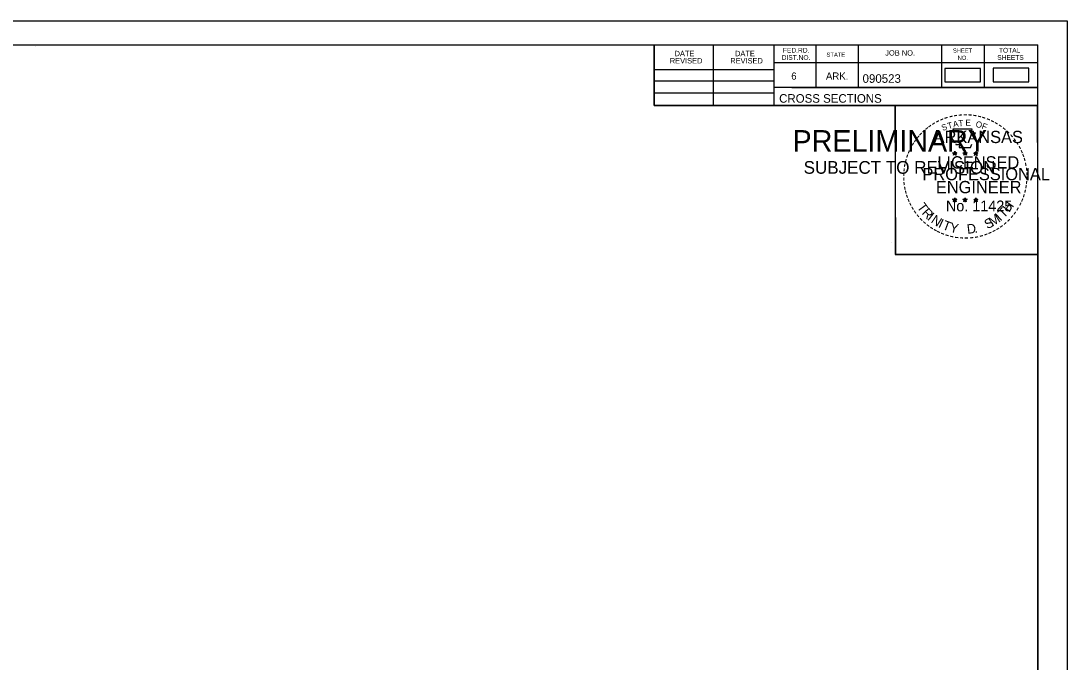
# Model space of a CAD drawing. Extents: x 1406028 to 1412453, y 321733 to 325986.
# Drawn here: x 1406582.1 to 1406752.8, y 323108.1 to 323212.7 of the extents above; entities that cross this region are included whole.
import ezdxf

# ---------------------------------------------------------------- set-up
doc = ezdxf.new("R2010")
doc.units = 0
for name, color, linetype in [('R_Border', 7, 'Continuous'), ('R_Border PE', 7, 'Continuous'), ('R_Border Prem', 7, 'Continuous'), ('R_Fin Surface', 7, 'Continuous'), ('R_No Plot', 7, 'Continuous')]:
    doc.layers.add(name, color=color, linetype=linetype)

msp = doc.modelspace()

# ---------------------------------------------------------------- linework, layer by layer
at = {"layer": 'R_Border'}
for p, q in [((1406431.89, 323208.8), (1406748.07, 323208.8)), ((1406685.43, 323198.92), (1406685.43, 323208.8)), ((1406695.11, 323198.92), (1406695.11, 323208.8)), ((1406704.97, 323208.8), (1406704.97, 323198.92)), ((1406711.81, 323208.8), (1406711.81, 323201.86)), ((1406718.75, 323208.8), (1406718.75, 323201.86)), ((1406732.33, 323208.8), (1406732.33, 323201.86)), ((1406739.27, 323208.8), (1406739.27, 323201.86)), ((1406748.07, 323003.34), (1406748.07, 323208.8)), ((1406584.41, 323208.54), (1406584.41, 323208.54)), ((1406584.41, 323208.54), (1406584.41, 323208.54)), ((1406748.07, 323205.86), (1406704.97, 323205.86)), ((1406748.07, 323205.88), (1406748.07, 323205.88)), ((1406685.43, 323204.78), (1406704.97, 323204.78)), ((1406685.43, 323202.92), (1406704.97, 323202.92)), ((1406685.43, 323200.98), (1406704.97, 323200.98)), ((1406748.07, 323201.86), (1406704.97, 323201.86)), ((1406707.93, 323201.86), (1406748.07, 323201.86)), ((1406748.07, 323198.92), (1406685.43, 323198.92))]:
    msp.add_line(p, q, dxfattribs=at)
at = {"layer": 'R_Border PE'}
for p, q in [((1406734.15, 323191.18), (1406734.5, 323191.07)), ((1406734.15, 323191.18), (1406734.41, 323191.13)), ((1406734.15, 323191.18), (1406734.39, 323191.05)), ((1406734.29, 323190.77), (1406734.5, 323191.07)), ((1406734.29, 323190.77), (1406734.41, 323191.01)), ((1406734.29, 323190.77), (1406734.5, 323190.99)), ((1406734.5, 323191.43), (1406734.46, 323191.18)), ((1406734.5, 323191.07), (1406734.5, 323191.43)), ((1406734.5, 323191.43), (1406734.55, 323191.18)), ((1406734.85, 323191.18), (1406734.5, 323191.07)), ((1406734.72, 323190.77), (1406734.5, 323191.07)), ((1406734.72, 323190.77), (1406734.5, 323190.98)), ((1406734.85, 323191.18), (1406734.56, 323191.13)), ((1406734.72, 323190.77), (1406734.58, 323191.06)), ((1406734.85, 323191.18), (1406734.65, 323191.07)), ((1406735.82, 323191.18), (1406736.17, 323191.07)), ((1406735.82, 323191.18), (1406736.08, 323191.13)), ((1406735.82, 323191.18), (1406736.06, 323191.05)), ((1406735.96, 323190.77), (1406736.17, 323191.07)), ((1406735.96, 323190.77), (1406736.08, 323191.01)), ((1406735.96, 323190.77), (1406736.17, 323190.99)), ((1406736.17, 323191.43), (1406736.13, 323191.18)), ((1406736.17, 323191.07), (1406736.17, 323191.43)), ((1406736.17, 323191.43), (1406736.22, 323191.18)), ((1406736.52, 323191.18), (1406736.17, 323191.07)), ((1406736.39, 323190.77), (1406736.17, 323191.07)), ((1406736.39, 323190.77), (1406736.17, 323190.98)), ((1406736.52, 323191.18), (1406736.23, 323191.13)), ((1406736.39, 323190.77), (1406736.25, 323191.06)), ((1406736.52, 323191.18), (1406736.32, 323191.07)), ((1406737.59, 323191.16), (1406737.94, 323191.05)), ((1406737.59, 323191.16), (1406737.84, 323191.12)), ((1406737.59, 323191.16), (1406737.83, 323191.04)), ((1406737.72, 323190.76), (1406737.94, 323191.05)), ((1406737.72, 323190.76), (1406737.85, 323191)), ((1406737.72, 323190.76), (1406737.94, 323190.97)), ((1406737.94, 323191.42), (1406737.9, 323191.17)), ((1406737.94, 323191.05), (1406737.94, 323191.42)), ((1406737.94, 323191.42), (1406737.99, 323191.17)), ((1406738.28, 323191.16), (1406737.94, 323191.05)), ((1406738.15, 323190.76), (1406737.94, 323191.05)), ((1406738.15, 323190.76), (1406737.94, 323190.97)), ((1406738.28, 323191.16), (1406738, 323191.12)), ((1406738.15, 323190.76), (1406738.01, 323191.05)), ((1406738.28, 323191.16), (1406738.08, 323191.06)), ((1406734.15, 323183.6), (1406734.5, 323183.49)), ((1406734.15, 323183.6), (1406734.4, 323183.56)), ((1406734.15, 323183.6), (1406734.39, 323183.48)), ((1406734.28, 323183.2), (1406734.5, 323183.49)), ((1406734.28, 323183.2), (1406734.41, 323183.44)), ((1406734.28, 323183.2), (1406734.5, 323183.41)), ((1406734.5, 323183.86), (1406734.46, 323183.61)), ((1406734.5, 323183.49), (1406734.5, 323183.86)), ((1406734.5, 323183.86), (1406734.55, 323183.61)), ((1406734.85, 323183.6), (1406734.5, 323183.49)), ((1406734.71, 323183.2), (1406734.5, 323183.49)), ((1406734.71, 323183.2), (1406734.5, 323183.41)), ((1406734.85, 323183.6), (1406734.56, 323183.55)), ((1406734.71, 323183.2), (1406734.58, 323183.49)), ((1406734.85, 323183.6), (1406734.64, 323183.5)), ((1406735.82, 323183.6), (1406736.17, 323183.49)), ((1406735.82, 323183.6), (1406736.07, 323183.56)), ((1406735.82, 323183.6), (1406736.06, 323183.48)), ((1406735.95, 323183.2), (1406736.17, 323183.49)), ((1406735.95, 323183.2), (1406736.08, 323183.44)), ((1406735.95, 323183.2), (1406736.17, 323183.41)), ((1406736.17, 323183.86), (1406736.13, 323183.61)), ((1406736.17, 323183.49), (1406736.17, 323183.86)), ((1406736.17, 323183.86), (1406736.22, 323183.61)), ((1406736.52, 323183.6), (1406736.17, 323183.49)), ((1406736.38, 323183.2), (1406736.17, 323183.49)), ((1406736.38, 323183.2), (1406736.17, 323183.41)), ((1406736.52, 323183.6), (1406736.23, 323183.55)), ((1406736.38, 323183.2), (1406736.24, 323183.49)), ((1406736.52, 323183.6), (1406736.31, 323183.5)), ((1406737.59, 323183.59), (1406737.94, 323183.48)), ((1406737.59, 323183.59), (1406737.84, 323183.55)), ((1406737.59, 323183.59), (1406737.82, 323183.47)), ((1406737.72, 323183.19), (1406737.94, 323183.48)), ((1406737.72, 323183.19), (1406737.85, 323183.43)), ((1406737.72, 323183.19), (1406737.93, 323183.4)), ((1406737.94, 323183.85), (1406737.89, 323183.6)), ((1406738.15, 323183.19), (1406737.93, 323183.4)), ((1406737.94, 323183.48), (1406737.94, 323183.85)), ((1406737.94, 323183.85), (1406737.98, 323183.6)), ((1406738.28, 323183.59), (1406737.94, 323183.48)), ((1406738.15, 323183.19), (1406737.94, 323183.48)), ((1406738.28, 323183.59), (1406738, 323183.54)), ((1406738.15, 323183.19), (1406738.01, 323183.48)), ((1406738.28, 323183.59), (1406738.08, 323183.49))]:
    msp.add_line(p, q, dxfattribs=at)
for points in [[(1406734.2, 323195.05), (1406734.46, 323194.23)], [(1406737.71, 323194.13), (1406737.85, 323194.42), (1406737.16, 323194.39), (1406737.31, 323195.05), (1406734.2, 323195.05)], [(1406734.69, 323192.63), (1406734.69, 323192.54), (1406735.25, 323192.53), (1406735.2, 323192.05), (1406737.07, 323192.05), (1406737.27, 323192.59)], [(1406734.5, 323191.43), (1406734.72, 323190.77), (1406734.15, 323191.18), (1406734.85, 323191.18), (1406734.29, 323190.77), (1406734.5, 323191.43)], [(1406736.17, 323191.43), (1406736.39, 323190.77), (1406735.82, 323191.18), (1406736.52, 323191.18), (1406735.96, 323190.77), (1406736.17, 323191.43)], [(1406737.94, 323191.42), (1406738.15, 323190.76), (1406737.59, 323191.16), (1406738.28, 323191.16), (1406737.72, 323190.76), (1406737.94, 323191.42)], [(1406734.5, 323183.86), (1406734.71, 323183.2), (1406734.15, 323183.6), (1406734.85, 323183.6), (1406734.28, 323183.2), (1406734.5, 323183.86)], [(1406736.17, 323183.86), (1406736.38, 323183.2), (1406735.82, 323183.6), (1406736.52, 323183.6), (1406735.95, 323183.2), (1406736.17, 323183.86)], [(1406737.94, 323183.85), (1406738.15, 323183.19), (1406737.59, 323183.59), (1406738.28, 323183.59), (1406737.72, 323183.19), (1406737.94, 323183.85)]]:
    msp.add_lwpolyline(points, dxfattribs=at)
for centre, radius in [((1406734.5, 323191.06), 0.172), ((1406734.5, 323191.06), 0.145), ((1406734.5, 323191.06), 0.116), ((1406734.5, 323191.06), 0.0991), ((1406734.5, 323191.06), 0.0747), ((1406734.5, 323191.06), 0.0495), ((1406734.5, 323191.06), 0.0296), ((1406736.17, 323191.06), 0.172), ((1406736.17, 323191.06), 0.145), ((1406736.17, 323191.06), 0.116), ((1406736.17, 323191.06), 0.0991), ((1406736.17, 323191.06), 0.0747), ((1406736.17, 323191.06), 0.0495), ((1406736.17, 323191.06), 0.0296), ((1406737.94, 323191.05), 0.172), ((1406737.94, 323191.05), 0.145), ((1406737.94, 323191.05), 0.116), ((1406737.94, 323191.05), 0.0991), ((1406737.94, 323191.05), 0.0747), ((1406737.94, 323191.05), 0.0495), ((1406737.94, 323191.05), 0.0296), ((1406734.5, 323183.49), 0.172), ((1406734.5, 323183.49), 0.145), ((1406734.5, 323183.49), 0.116), ((1406734.5, 323183.49), 0.0991), ((1406734.5, 323183.49), 0.0747), ((1406734.5, 323183.49), 0.0495), ((1406734.5, 323183.49), 0.0296), ((1406736.17, 323183.49), 0.172), ((1406736.17, 323183.49), 0.145), ((1406736.17, 323183.49), 0.116), ((1406736.17, 323183.49), 0.0991), ((1406736.17, 323183.49), 0.0747), ((1406736.17, 323183.49), 0.0495), ((1406736.17, 323183.49), 0.0296), ((1406737.93, 323183.48), 0.172), ((1406737.93, 323183.48), 0.145), ((1406737.93, 323183.48), 0.116), ((1406737.93, 323183.48), 0.0991), ((1406737.93, 323183.48), 0.0747), ((1406737.93, 323183.48), 0.0495), ((1406737.93, 323183.48), 0.0296)]:
    msp.add_circle(centre, radius, dxfattribs=at)
at = {"layer": 'R_Fin Surface'}
for points in [[(1406732.85, 323202.75), (1406738.68, 323202.75), (1406738.68, 323204.94), (1406732.85, 323204.94)], [(1406740.76, 323202.78), (1406746.59, 323202.78), (1406746.59, 323204.97), (1406740.76, 323204.97)]]:
    msp.add_lwpolyline(points, close=True, dxfattribs=at)
at = {"layer": 'R_No Plot'}
for p, q in [((1406419.49, 323212.7), (1406752.82, 323212.7)), ((1406724.1, 323176.47), (1406724.1, 323176.47))]:
    msp.add_line(p, q, dxfattribs=at)
for points in [[(1406419.48, 323212.7), (1406752.82, 323212.7), (1406752.82, 322999.36), (1406419.48, 322999.36)], [(1406665.81, 323208.8), (1406685.43, 323208.8), (1406685.43, 323198.92), (1406701.54, 323198.92), (1406724.74, 323198.92), (1406724.74, 323174.59), (1406748.07, 323174.59), (1406748.07, 323003.34), (1406431.89, 323003.34), (1406431.89, 323208.8)], [(1406724.74, 323198.92), (1406747.95, 323198.92), (1406748.07, 323174.59), (1406724.86, 323174.59)]]:
    msp.add_lwpolyline(points, close=True, dxfattribs=at)

# ---------------------------------------------------------------- texts
at = {"layer": 'R_Border'}
for s, height, p in [('DATE', 0.879, (1406688.77, 323206.94)), ('DATE', 0.879, (1406698.63, 323206.94)), ('DIST.NO.', 0.782, (1406706.25, 323206.34)), ('FED.RD.', 0.782, (1406706.45, 323207.52)), ('STATE', 0.684, (1406713.57, 323206.84)), ('JOB NO.', 0.879, (1406723.15, 323207.04)), ('SHEET', 0.684, (1406734.19, 323207.52)), ('SHEETS', 0.782, (1406741.43, 323206.34)), ('TOTAL', 0.782, (1406741.71, 323207.52)), ('REVISED', 0.879, (1406687.99, 323205.76)), ('REVISED', 0.879, (1406697.85, 323205.76)), ('NO.', 0.684, (1406734.97, 323206.34)), ('6', 1.17, (1406707.81, 323203.12)), ('ARK.', 1.172, (1406713.47, 323203.12)), ('090523', 1.4, (1406719.45, 323202.6)), ('CROSS SECTIONS', 1.4, (1406705.83, 323199.35))]:
    msp.add_text(s, height=height, rotation=360, dxfattribs=at).set_placement(p)
at = {"layer": 'R_Border PE'}
for s, height, rotation, p in [('-', 1.6, 19.1761, (1406732.94, 323196.18)), ('-', 1.6, 13.6301, (1406733.69, 323196.42)), ('-', 1.6, 10.2193, (1406734.37, 323196.58)), ('-', 1.6, 5.8968, (1406735.1, 323196.69)), ('-', 1.6, 0.1862, (1406735.87, 323196.77)), ('-', 1.6, 357.743, (1406736.6, 323196.75)), ('-', 1.6, 352.1617, (1406737.34, 323196.7)), ('-', 1.6, 347.2049, (1406738.06, 323196.58)), ('-', 1.6, 342.3362, (1406738.69, 323196.43)), ('-', 1.6, 337.8551, (1406739.43, 323196.21)), ('-', 1.6, 38.9507, (1406730.03, 323194.45)), ('-', 1.6, 36.2317, (1406730.5, 323194.83)), ('-', 1.6, 34.0636, (1406731.08, 323195.23)), ('-', 1.6, 28.7918, (1406731.68, 323195.6)), ('-', 1.6, 24.3072, (1406732.31, 323195.91)), ('S', 1, 21.594, (1406732.55, 323194.73)), ('T', 1, 16.4036, (1406733.46, 323195.06)), ('A', 1, 11.2132, (1406734.29, 323195.31)), ('T', 1, 6.0228, (1406735.14, 323195.48)), ('E', 1, 0.8323, (1406736.24, 323195.59)), ('O', 1, 350.4515, (1406737.85, 323195.38)), ('F', 1, 340.0707, (1406738.8, 323195.15)), ('-', 1.6, 334.1211, (1406740.06, 323195.93)), ('-', 1.6, 329.6409, (1406740.64, 323195.65)), ('-', 1.6, 325.8627, (1406741.28, 323195.29)), ('-', 1.6, 320.5297, (1406741.89, 323194.86)), ('-', 1.6, 54.2325, (1406728.33, 323192.5)), ('-', 1.6, 50.6142, (1406728.74, 323193.07)), ('-', 1.6, 48.423, (1406729.14, 323193.56)), ('-', 1.6, 42.9622, (1406729.59, 323194.04)), ('ARKANSAS', 2, 360, (1406731.05, 323192.77)), ('-', 1.6, 315.5786, (1406742.49, 323194.38)), ('-', 1.6, 309.8797, (1406743.06, 323193.83)), ('-', 1.6, 306.6522, (1406743.58, 323193.22)), ('-', 1.6, 62.8713, (1406727.69, 323191.36)), ('-', 1.6, 58.0706, (1406728, 323191.98)), ('-', 1.4, 303.6753, (1406744.07, 323192.66)), ('-', 1.6, 299.6684, (1406744.39, 323192.05)), ('-', 1.6, 75.461, (1406727.02, 323189.41)), ('-', 1.6, 72.3945, (1406727.21, 323190.12)), ('-', 1.6, 67.7743, (1406727.43, 323190.75)), ('LICENSED', 2, 360, (1406731.65, 323188.62)), ('DWB', 0.01, 360, (1406734.49, 323191.06)), ('DWB', 0.01, 360, (1406736.16, 323191.06)), ('DWB', 0.01, 360, (1406737.92, 323191.05)), ('-', 1.6, 294.6628, (1406744.71, 323191.44)), ('-', 1.6, 290.5728, (1406744.97, 323190.86)), ('-', 1.6, 285.1233, (1406745.2, 323190.28)), ('-', 1.6, 85.1863, (1406726.81, 323188)), ('-', 1.6, 81.2013, (1406726.88, 323188.7)), ('PROFESSIONAL', 2, 360, (1406729.22, 323186.71)), ('-', 1.6, 280.5493, (1406745.4, 323189.54)), ('-', 1.6, 276.5962, (1406745.57, 323188.77)), ('-', 1.6, 94.1959, (1406726.82, 323186.58)), ('-', 1.6, 89.0622, (1406726.78, 323187.3)), ('ENGINEER', 2, 360, (1406731.41, 323184.59)), ('-', 1.6, 263.5172, (1406745.64, 323186.75)), ('-', 1.6, 274.3301, (1406745.63, 323188.05)), ('-', 1.6, 269.9407, (1406745.66, 323187.42)), ('-', 1.6, 98.9479, (1406726.89, 323185.91)), ('-', 1.6, 101.7149, (1406727.02, 323185.18)), ('-', 1.6, 105.4578, (1406727.19, 323184.58)), ('-', 1.6, 255.7626, (1406745.46, 323185.42)), ('-', 1.6, 260.9953, (1406745.57, 323186.1)), ('-', 1.6, 109.0874, (1406727.4, 323183.95)), ('-', 1.6, 114.0643, (1406727.66, 323183.36)), ('T', 1.54, 306.0406, (1406728.26, 323182.33)), ('No. 11425', 1.757, 360, (1406733.04, 323181.64)), ('DWB', 0.01, 360, (1406734.49, 323183.49)), ('DWB', 0.01, 360, (1406736.16, 323183.49)), ('DWB', 0.01, 360, (1406737.92, 323183.48)), ('H', 1.54, 54.6088, (1406743.38, 323181.37)), ('-', 1.6, 247.8887, (1406745.06, 323184.03)), ('-', 1.6, 252.8681, (1406745.28, 323184.7)), ('-', 1.6, 115.7289, (1406727.96, 323182.74)), ('-', 1.6, 120.4471, (1406728.32, 323182.15)), ('-', 1.6, 125.8934, (1406728.72, 323181.59)), ('R', 1.54, 314.005, (1406729.02, 323181.28)), ('T', 1.54, 46.6444, (1406742.49, 323180.42)), ('-', 1.6, 233.8452, (1406744, 323181.99)), ('-', 1.6, 239.0712, (1406744.4, 323182.64)), ('-', 1.6, 244.6197, (1406744.79, 323183.4)), ('-', 1.6, 130.7181, (1406729.18, 323181.04)), ('-', 1.6, 134.2238, (1406729.7, 323180.49)), ('-', 1.6, 138.9338, (1406730.22, 323180.03)), ('I', 1.54, 321.9694, (1406729.92, 323180.35)), ('N', 1.54, 326.5002, (1406730.49, 323179.88)), ('I', 1.54, 335.3603, (1406731.7, 323179.09)), ('T', 1.54, 339.8912, (1406732.36, 323178.77)), ('Y', 1.54, 347.8556, (1406733.58, 323178.32)), ('S', 1.54, 26.9312, (1406739.8, 323178.69)), ('M', 1.54, 32.6563, (1406740.64, 323179.1)), ('I', 1.54, 42.1136, (1406741.93, 323179.95)), ('-', 1.6, 221.0851, (1406742.57, 323180.35)), ('-', 1.6, 225.7653, (1406743.09, 323180.86)), ('-', 1.6, 231.2538, (1406743.57, 323181.43)), ('-', 1.6, 144.6463, (1406730.78, 323179.62)), ('-', 1.6, 148.0898, (1406731.34, 323179.25)), ('-', 1.6, 151.5704, (1406731.92, 323178.93)), ('-', 1.6, 154.6002, (1406732.44, 323178.68)), ('-', 1.6, 158.5612, (1406733.07, 323178.43)), ('D', 1.54, 6.3969, (1406736.56, 323177.96)), ('.', 1.54, 13.7642, (1406737.75, 323178.09)), ('-', 1.6, 204.2516, (1406740.3, 323178.83)), ('-', 1.6, 207.3568, (1406740.93, 323179.15)), ('-', 1.6, 212.2491, (1406741.48, 323179.49)), ('-', 1.6, 215.7363, (1406742.02, 323179.88)), ('-', 1.6, 162.7983, (1406733.75, 323178.21)), ('-', 1.6, 167.5555, (1406734.47, 323178.05)), ('-', 1.6, 173.1155, (1406735.24, 323177.94)), ('-', 1.6, 176.5183, (1406735.99, 323177.89)), ('-', 1.6, 181.5918, (1406736.73, 323177.91)), ('-', 1.6, 185.8167, (1406737.54, 323177.98)), ('-', 1.6, 191.2858, (1406738.28, 323178.11)), ('-', 1.6, 195.4743, (1406739.01, 323178.31)), ('-', 1.6, 200.7184, (1406739.68, 323178.56))]:
    msp.add_text(s, height=height, rotation=rotation, dxfattribs=at).set_placement(p)
at = {"layer": 'R_Border Prem'}
for s, height, p in [('PRELIMINARY', 3.5, (1406708.02, 323191.38)), ('DWB', 0.01, (1406708.77, 323193.23)), ('SUBJECT TO REVISION', 2.0751, (1406709.83, 323187.76))]:
    msp.add_text(s, height=height, rotation=360, dxfattribs=at).set_placement(p)

doc.saveas('drawing.dxf')
